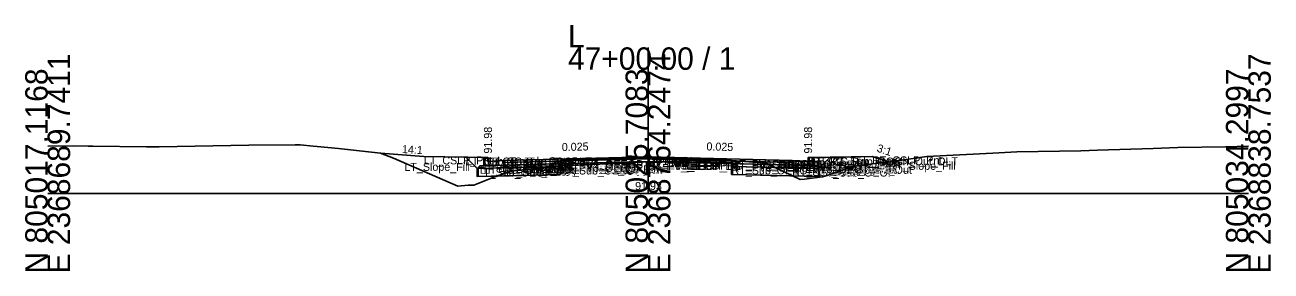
# Model space of a CAD drawing. Extents: x -26 to 8153, y -10 to 9520.
# Drawn here: x 3997.2 to 4152.8, y 3990.3 to 4021 of the extents above; entities that cross this region are included whole.
import ezdxf

# ---------------------------------------------------------------- set-up
doc = ezdxf.new("R2010")
doc.units = 0
for name, color, linetype in [('Exist CMT Pavement', 7, 'Continuous'), ('Exist Cross Section Cell', 7, 'Continuous'), ('Exist XS Center Line Elevation Label', 7, 'Continuous'), ('Exist XS Ground Line', 7, 'Continuous'), ('Prop CMT Conc Surface', 7, 'Continuous'), ('Prop CMT Concrete Structures', 7, 'Continuous'), ('Prop CMT Pvmt Course 1', 7, 'Continuous'), ('Prop CMT Pvmt Course 1 CG', 7, 'Continuous'), ('Prop CMT Pvmt Course 1 Wedge', 7, 'Continuous'), ('Prop CMT Pvmt Course 2', 7, 'Continuous'), ('Prop CMT Pvmt Course 2 Wedge', 7, 'Continuous'), ('Prop CMT Pvmt Course 3', 7, 'Continuous'), ('Prop CMT Pvmt Course 3 Wedge', 7, 'Continuous'), ('Prop CMT Pvmt Surface', 7, 'Continuous'), ('Prop CMT Pvmt Wedge Surface 1', 7, 'Continuous'), ('Prop CMT Pvmt Wedge Surface 2', 7, 'Continuous'), ('Prop CMT Pvmt Wedge Surface 3', 7, 'Continuous'), ('Prop CMT Shallow Undercut', 7, 'Continuous'), ('Prop CMT Shallow Undercut Boundary', 7, 'Continuous'), ('Prop CMT Slope Grass', 7, 'Continuous'), ('Prop CMT Subgrade Earthwork', 7, 'Continuous'), ('Prop XS Earthwork Shape', 7, 'Continuous'), ('Prop XS Hydro Elevations', 7, 'Continuous'), ('Prop XS SE Text', 7, 'Continuous'), ('Prop XS Side Slope Text', 7, 'Continuous'), ('Prop XS Subgrade Earthwork', 7, 'Continuous'), ('Scratch_Level_2', 7, 'Continuous'), ('Scratch_Level_6', 7, 'Continuous')]:
    doc.layers.add(name, color=color, linetype=linetype)

msp = doc.modelspace()

# ---------------------------------------------------------------- linework, layer by layer
at = {"layer": 'Exist CMT Pavement'}
for p, q in [((4079.54, 4004.02), (4085.44, 4004.13)), ((4064.06, 4003.49), (4070.23, 4003.71)), ((4070.23, 4003.71), (4074.96, 4003.93)), ((4074.96, 4003.93), (4079.54, 4004.02))]:
    msp.add_line(p, q, dxfattribs=at)
at = {"layer": 'Exist Cross Section Cell'}
for p, q in [((4075, 4000), (4075, 4018.24)), ((4000, 4000), (4075, 4000)), ((4075, 4000), (4150, 4000))]:
    msp.add_line(p, q, dxfattribs=at)
at = {"layer": 'Exist XS Ground Line'}
for p, q in [((4000, 4005.91), (4003.28, 4005.93)), ((4003.28, 4005.93), (4005.06, 4005.92)), ((4005.06, 4005.92), (4005.63, 4005.92)), ((4005.63, 4005.92), (4012.33, 4005.84)), ((4012.33, 4005.84), (4013.93, 4005.83)), ((4013.93, 4005.83), (4025.14, 4006.04)), ((4025.14, 4006.04), (4030.92, 4006.06)), ((4030.92, 4006.06), (4031.53, 4006.06)), ((4031.53, 4006.06), (4033.16, 4005.9)), ((4033.16, 4005.9), (4033.66, 4005.88)), ((4033.66, 4005.88), (4035, 4005.74)), ((4035, 4005.74), (4036.34, 4005.61)), ((4138.1, 4005.62), (4141.21, 4005.72)), ((4141.21, 4005.72), (4147.13, 4005.83)), ((4147.13, 4005.83), (4150, 4005.92)), ((4036.34, 4005.61), (4041.59, 4005.01)), ((4041.59, 4005.01), (4043.21, 4004.41)), ((4043.21, 4004.41), (4051.26, 4000.91)), ((4079.54, 4004.02), (4085.44, 4004.13)), ((4085.44, 4004.13), (4089.75, 4003.78)), ((4105.82, 4004.05), (4109.85, 4004.61)), ((4109.85, 4004.61), (4118.08, 4005.02)), ((4118.08, 4005.02), (4121.08, 4005.19)), ((4121.08, 4005.19), (4129.08, 4005.34)), ((4129.08, 4005.34), (4131.15, 4005.39)), ((4131.15, 4005.39), (4138.1, 4005.62)), ((4055.72, 4002.02), (4057.74, 4002.74)), ((4057.74, 4002.74), (4059.1, 4002.95)), ((4059.1, 4002.95), (4059.6, 4002.9)), ((4059.6, 4002.9), (4060.72, 4003.07)), ((4060.72, 4003.07), (4064.06, 4003.49)), ((4064.06, 4003.49), (4070.23, 4003.71)), ((4070.23, 4003.71), (4074.96, 4003.93)), ((4074.96, 4003.93), (4079.54, 4004.02)), ((4089.75, 4003.78), (4094, 4001.75)), ((4097.38, 4002.24), (4100.71, 4003.42)), ((4100.71, 4003.42), (4105.82, 4004.05)), ((4051.26, 4000.91), (4052.54, 4001.04)), ((4052.54, 4001.04), (4053.26, 4001.05)), ((4053.26, 4001.05), (4055.72, 4002.02)), ((4094, 4001.75), (4094.54, 4001.8)), ((4094.54, 4001.8), (4096.82, 4002.06)), ((4096.82, 4002.06), (4097.38, 4002.24))]:
    msp.add_line(p, q, dxfattribs=at)
at = {"layer": 'Prop CMT Conc Surface'}
for points in [[(4055, 4003.98), (4055, 4004.48), (4054.5, 4004.48)], [(4095, 4003.98), (4095, 4004.48), (4095.5, 4004.48)], [(4057, 4004.11), (4055, 4003.98)], [(4093, 4004.11), (4095, 4003.98)]]:
    msp.add_lwpolyline(points, dxfattribs=at)
at = {"layer": 'Prop CMT Concrete Structures'}
for points in [[(4057, 4004.11), (4055, 4003.98), (4055, 4004.48), (4054.5, 4004.48)], [(4054.5, 4004.48), (4054.5, 4003.46), (4057, 4003.52)], [(4093, 4004.11), (4095, 4003.98), (4095, 4004.48), (4095.5, 4004.48)], [(4095.5, 4004.48), (4095.5, 4003.46), (4093, 4003.52)], [(4057, 4003.52), (4057, 4004.11)], [(4093, 4003.52), (4093, 4004.11)]]:
    msp.add_lwpolyline(points, dxfattribs=at)
at = {"layer": 'Prop CMT Pvmt Course 1'}
for points in [[(4075, 4004.56), (4057, 4004.11)], [(4064.06, 4004.16), (4075, 4004.43)], [(4064.06, 4004.03), (4064.06, 4004.16)], [(4075, 4004.31), (4075, 4004.56)], [(4075, 4004.56), (4093, 4004.11)], [(4075, 4004.31), (4075, 4004.56)], [(4075, 4004.43), (4075, 4004.31), (4075, 4004.31)], [(4085.44, 4004.17), (4075, 4004.43)], [(4075, 4004.43), (4075, 4004.31), (4075, 4004.31)], [(4085.44, 4004.05), (4085.44, 4004.17)], [(4057, 4004.11), (4057, 4003.86)], [(4057, 4003.86), (4064.06, 4004.03)], [(4093, 4003.86), (4085.44, 4004.05)], [(4093, 4004.11), (4093, 4003.86)]]:
    msp.add_lwpolyline(points, dxfattribs=at)
at = {"layer": 'Prop CMT Pvmt Course 1 CG'}
for points in [[(4057, 4003.52), (4054, 4003.45), (4053.66, 4003.11)], [(4053.66, 4003.11), (4057, 4003.2)], [(4057, 4003.2), (4057, 4003.52)], [(4093, 4003.52), (4096, 4003.45), (4096.34, 4003.11)], [(4093, 4003.2), (4093, 4003.52)], [(4096.34, 4003.11), (4093, 4003.2)]]:
    msp.add_lwpolyline(points, dxfattribs=at)
at = {"layer": 'Prop CMT Pvmt Course 1 Wedge'}
for points in [[(4075, 4004.43), (4064.06, 4004.16)], [(4075, 4004.43), (4085.44, 4004.17)]]:
    msp.add_lwpolyline(points, dxfattribs=at)
at = {"layer": 'Prop CMT Pvmt Course 2'}
for points in [[(4064.06, 4004.03), (4057, 4003.86)], [(4057, 4003.86), (4057, 4003.53)], [(4057, 4003.53), (4064.06, 4003.7)], [(4064.06, 4003.7), (4064.06, 4004.03)], [(4085.44, 4003.72), (4085.44, 4004.05)], [(4085.44, 4004.05), (4093, 4003.86)], [(4093, 4003.53), (4085.44, 4003.72)], [(4093, 4003.86), (4093, 4003.53)]]:
    msp.add_lwpolyline(points, dxfattribs=at)
at = {"layer": 'Prop CMT Pvmt Course 2 Wedge'}
for points in [[(4075, 4004.31), (4064.06, 4004.03)], [(4075, 4004.31), (4085.44, 4004.05)]]:
    msp.add_lwpolyline(points, dxfattribs=at)
at = {"layer": 'Prop CMT Pvmt Course 3'}
for points in [[(4064.06, 4003.7), (4057, 4003.53)], [(4057, 4003.53), (4057, 4003.2)], [(4057, 4003.2), (4064.06, 4003.37)], [(4064.06, 4003.37), (4064.06, 4003.7)], [(4085.44, 4003.72), (4093, 4003.53)], [(4085.44, 4003.38), (4085.44, 4003.72)], [(4093, 4003.2), (4085.44, 4003.38)], [(4093, 4003.53), (4093, 4003.2)]]:
    msp.add_lwpolyline(points, dxfattribs=at)
at = {"layer": 'Prop CMT Pvmt Course 3 Wedge'}
for points in [[(4075, 4003.98), (4064.06, 4003.7)], [(4075, 4003.98), (4085.44, 4003.72)]]:
    msp.add_lwpolyline(points, dxfattribs=at)
at = {"layer": 'Prop CMT Pvmt Surface'}
for points in [[(4075, 4004.56), (4057, 4004.11)], [(4075, 4004.56), (4093, 4004.11)]]:
    msp.add_lwpolyline(points, dxfattribs=at)
at = {"layer": 'Prop CMT Pvmt Wedge Surface 1'}
for points in [[(4075, 4004.43), (4064.06, 4004.16)], [(4064.06, 4004.16), (4064.06, 4004.03)], [(4075, 4004.43), (4085.44, 4004.17)], [(4085.44, 4004.17), (4085.44, 4004.05)], [(4057, 4003.86), (4057, 4004.11)], [(4064.06, 4004.03), (4057, 4003.86)], [(4085.44, 4004.05), (4093, 4003.86)], [(4093, 4003.86), (4093, 4004.11)]]:
    msp.add_lwpolyline(points, dxfattribs=at)
at = {"layer": 'Prop CMT Pvmt Wedge Surface 2'}
for points in [[(4075, 4004.31), (4057, 4003.86)], [(4075, 4004.31), (4093, 4003.86)], [(4057, 4003.86), (4057, 4004.11)], [(4093, 4003.86), (4093, 4004.11)]]:
    msp.add_lwpolyline(points, dxfattribs=at)
at = {"layer": 'Prop CMT Pvmt Wedge Surface 3'}
for points in [[(4057, 4003.53), (4057, 4004.11)], [(4075, 4003.98), (4057, 4003.53)], [(4075, 4003.98), (4093, 4003.53)], [(4093, 4003.53), (4093, 4004.11)]]:
    msp.add_lwpolyline(points, dxfattribs=at)
at = {"layer": 'Prop CMT Shallow Undercut'}
for points in [[(4064.06, 4003.37), (4064.06, 4002.37), (4056.15, 4002.17), (4057.74, 4002.74), (4059.1, 4002.95), (4059.6, 4002.9), (4060.72, 4003.07), (4062.93, 4003.34)], [(4090.87, 4003.25), (4093.07, 4002.19), (4085.44, 4002.38), (4085.44, 4003.38)]]:
    msp.add_lwpolyline(points, close=True, dxfattribs=at)
at = {"layer": 'Prop CMT Shallow Undercut Boundary'}
for p, q in [((4053.66, 4003.11), (4053.66, 4002.11)), ((4064.06, 4003.37), (4064.06, 4002.37)), ((4085.44, 4003.38), (4085.44, 4002.38)), ((4096.34, 4003.11), (4096.34, 4002.11)), ((4053.66, 4002.11), (4064.06, 4002.37)), ((4085.44, 4002.38), (4096.34, 4002.11))]:
    msp.add_line(p, q, dxfattribs=at)
at = {"layer": 'Prop CMT Slope Grass'}
for points in [[(4054.5, 4004.48), (4047, 4004.63), (4041.59, 4005.01)], [(4095.5, 4004.48), (4103, 4004.63), (4105.04, 4003.95)]]:
    msp.add_lwpolyline(points, dxfattribs=at)
at = {"layer": 'Prop CMT Subgrade Earthwork'}
for points in [[(4057, 4003.2), (4053.66, 4003.11), (4052.25, 4004.52)], [(4085.44, 4003.38), (4085.42, 4004.13)], [(4093, 4003.2), (4096.34, 4003.11), (4097.75, 4004.52)], [(4064.06, 4003.37), (4057, 4003.2)], [(4064.06, 4003.37), (4064.08, 4003.49)], [(4085.44, 4003.38), (4093, 4003.2)]]:
    msp.add_lwpolyline(points, dxfattribs=at)
at = {"layer": 'Prop XS Earthwork Shape'}
for points in [[(4051.26, 4000.91), (4052.54, 4001.04), (4053.26, 4001.05), (4055.72, 4002.02), (4056.15, 4002.17), (4053.66, 4002.11), (4053.66, 4003.11), (4052.25, 4004.52), (4047, 4004.63), (4041.59, 4005.01), (4043.21, 4004.41)], [(4085.42, 4004.13), (4085.44, 4004.13), (4089.75, 4003.78), (4090.87, 4003.25), (4085.44, 4003.38)], [(4096.34, 4003.11), (4096.34, 4002.11), (4093.07, 4002.19), (4094, 4001.75), (4094.54, 4001.8), (4096.82, 4002.06), (4097.38, 4002.24), (4100.71, 4003.42), (4105.04, 4003.95), (4103, 4004.63), (4097.75, 4004.52)], [(4059.1, 4002.95), (4059.6, 4002.9), (4060.72, 4003.07), (4062.93, 4003.34), (4057, 4003.2), (4053.66, 4003.11), (4053.66, 4002.11), (4056.15, 4002.17), (4057.74, 4002.74)], [(4059.1, 4002.95), (4059.6, 4002.9), (4060.72, 4003.07), (4062.93, 4003.34), (4064.06, 4003.37), (4064.06, 4002.37), (4056.15, 4002.17), (4057.74, 4002.74)], [(4062.93, 4003.34), (4064.06, 4003.49), (4064.08, 4003.49), (4064.06, 4003.37)], [(4085.44, 4003.38), (4085.44, 4002.38), (4093.07, 4002.19), (4090.87, 4003.25)], [(4096.34, 4003.11), (4096.34, 4002.11), (4093.07, 4002.19), (4090.87, 4003.25), (4093, 4003.2)]]:
    msp.add_lwpolyline(points, close=True, dxfattribs=at)
at = {"layer": 'Prop XS Subgrade Earthwork'}
for p, q in [((4053.66, 4003.11), (4064.06, 4003.37)), ((4085.44, 4003.38), (4096.34, 4003.11))]:
    msp.add_line(p, q, dxfattribs=at)
at = {"layer": 'Scratch_Level_6'}
for points in [[(4064.06, 4003.37), (4064.06, 4002.37), (4056.15, 4002.17), (4057.74, 4002.74), (4059.1, 4002.95), (4059.6, 4002.9), (4060.72, 4003.07), (4062.93, 4003.34)], [(4090.87, 4003.25), (4093.07, 4002.19), (4085.44, 4002.38), (4085.44, 4003.38)]]:
    msp.add_lwpolyline(points, close=True, dxfattribs=at)

# ---------------------------------------------------------------- texts
at = {"layer": 'Exist Cross Section Cell'}
for s, p in [('L', (4065, 4018.24)), ('47+00.00 / 1', (4065, 4015.44))]:
    msp.add_text(s, height=2.8, dxfattribs=at).set_placement(p)
for s, p in [('E 2368689.7411', (4002.8, 3990)), ('E 2368764.2474', (4077.8, 3990)), ('E 2368838.7537', (4152.8, 3990)), ('N 805017.1168', (4000, 3990)), ('N 805025.7083', (4075, 3990)), ('N 805034.2997', (4150, 3990))]:
    msp.add_text(s, height=2.8, rotation=90, dxfattribs=at).set_placement(p)
at = {"layer": 'Exist XS Center Line Elevation Label'}
msp.add_text('91.93', height=1, dxfattribs=at).set_placement((4073.39, 4000.43))
at = {"layer": 'Prop XS Hydro Elevations'}
for p in [(4055.5, 4004.98), (4095.5, 4004.98)]:
    msp.add_text('91.98', height=1, rotation=90, dxfattribs=at).set_placement(p)
at = {"layer": 'Prop XS SE Text'}
for rotation, p in [(1.4321, (4064.24, 4005.29)), (358.5679, (4082.29, 4005.38))]:
    msp.add_text('0.025', height=1, rotation=rotation, dxfattribs=at).set_placement(p)
at = {"layer": 'Prop XS Side Slope Text'}
for s, rotation, p in [('14:1', 356.7486, (4044.24, 4005.05)), ('3:1', 341.5651, (4103.5, 4005.25))]:
    msp.add_text(s, height=1, rotation=rotation, dxfattribs=at).set_placement(p)
at = {"layer": 'Scratch_Level_2'}
for s, p in [('LT_CSLP_Pnt', (4047, 4003.63)), ('LT_Sub_Trench_Out_DLT', (4052.25, 4003.52)), ('LT_CG_Top_BOC', (4054.5, 4003.48)), ('LT_CG_Top_Face', (4055, 4003.48)), ('LT_PV1_OEEOP', (4064.06, 4003.16)), ('PV1_PGL', (4075, 4003.56)), ('RT_PV1_IEEOP', (4075, 4003.43)), ('LT_PV1_IEEOP', (4075, 4003.43)), ('RT_PV2_IEEOP', (4075, 4003.31)), ('LT_PV2_IEEOP', (4075, 4003.31)), ('PV2_PGL', (4075, 4003.31)), ('RT_PV_Sub_Tie_Out', (4085.42, 4003.13)), ('RT_PV1_OEEOP', (4085.44, 4003.17)), ('RT_PV_OEEOP_EG', (4085.44, 4003.13)), ('RT_CG_Top_Face', (4095, 4003.48)), ('RT_CG_Top_BOC', (4095.5, 4003.48)), ('RT_Sub_Trench_Out_DLT', (4097.75, 4003.52)), ('RT_CSLP_Pnt', (4103, 4003.63)), ('LT_Slope_Fill', (4044.57, 4002.82)), ('LT_Sub_OEOP', (4053.66, 4002.11)), ('LT_CG1_Shelf_Out', (4054, 4002.45)), ('LT_CG_Bot_BOC', (4054.5, 4002.46)), ('LT_CG_Top_Gut', (4055, 4002.98)), ('LT_PV1_OEOT', (4057, 4003.11)), ('LT_PV2_OEOT', (4057, 4002.86)), ('LT_PV3_OEOT', (4057, 4002.53)), ('LT_CG_Bot_IE', (4057, 4002.52)), ('LT_Sub_OEOT', (4057, 4002.2)), ('LT_PV2_OEEOP', (4064.06, 4003.03)), ('LT_PV3_OEEOP', (4064.06, 4002.7)), ('LT_PV_OEEOP_EG', (4064.06, 4002.49)), ('LT_Sub_OEEOP', (4064.06, 4002.37)), ('LT_PV_Sub_Tie_Out', (4064.08, 4002.49)), ('RT_PV3_IEEOP', (4075, 4002.98)), ('LT_PV3_IEEOP', (4075, 4002.98)), ('RT_PV_IEEOP_EG', (4075, 4002.93)), ('LT_PV_IEEOP_EG', (4075, 4002.93)), ('RT_PV2_OEEOP', (4085.44, 4003.05)), ('RT_PV3_OEEOP', (4085.44, 4002.72)), ('RT_Sub_OEEOP', (4085.44, 4002.38)), ('RT_PV1_OEOT', (4093, 4003.11)), ('RT_PV2_OEOT', (4093, 4002.86)), ('RT_PV3_OEOT', (4093, 4002.53)), ('RT_CG_Bot_IE', (4093, 4002.52)), ('RT_Sub_OEOT', (4093, 4002.2)), ('RT_CG_Top_Gut', (4095, 4002.98)), ('RT_CG_Bot_BOC', (4095.5, 4002.46)), ('RT_CG1_Shelf_Out', (4096, 4002.45)), ('RT_Sub_OEOP', (4096.34, 4002.11)), ('RT_Slope_Fill', (4105.04, 4002.95))]:
    msp.add_text(s, height=1, dxfattribs=at).set_placement(p)

doc.saveas('drawing.dxf')
